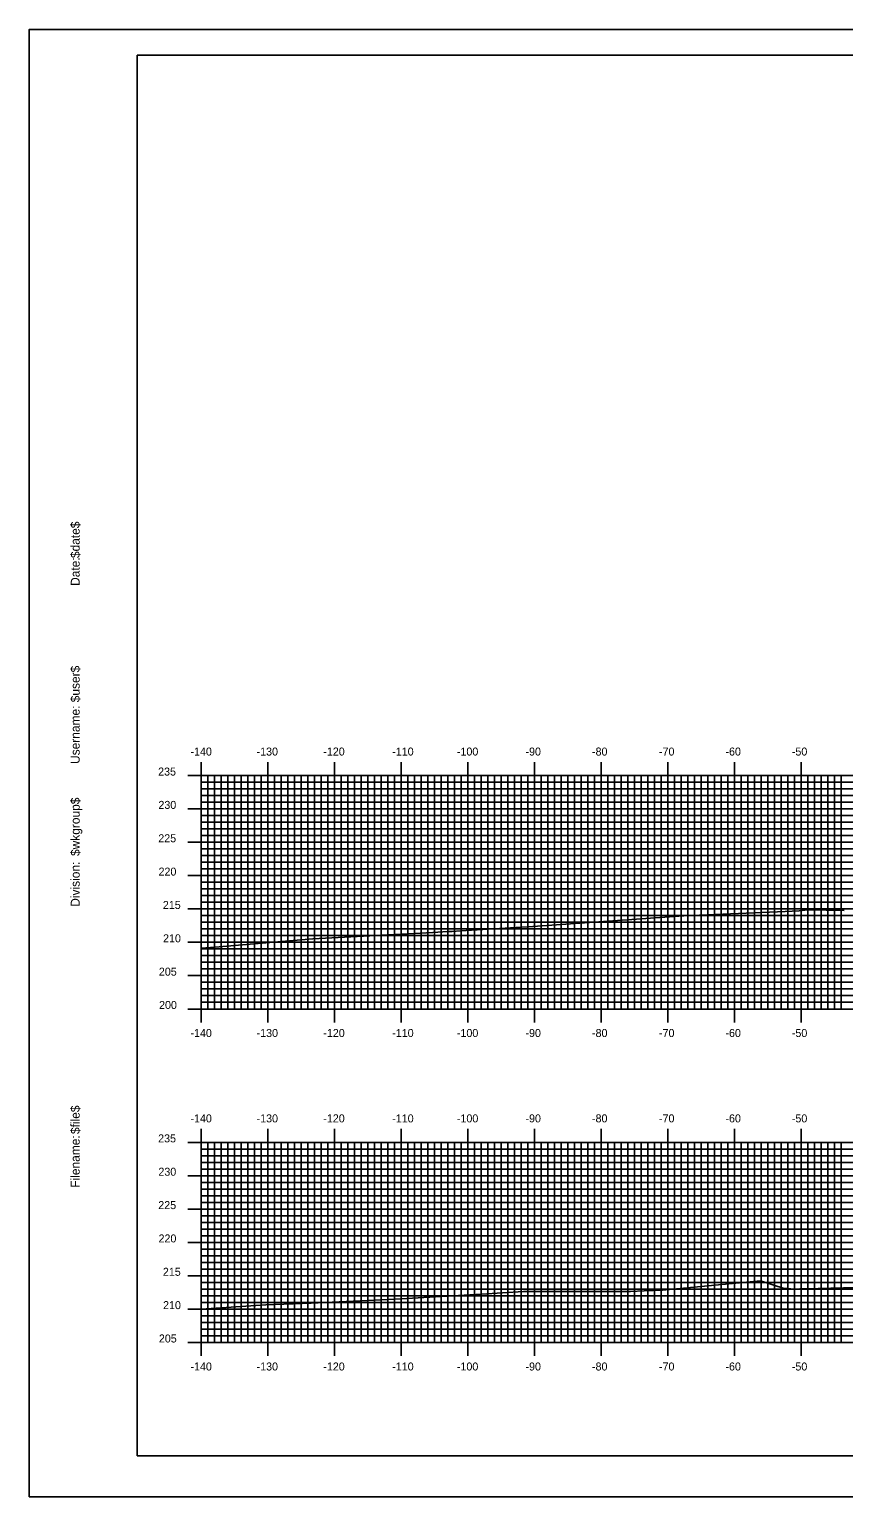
# Model space of a CAD drawing. Extents: x 851348 to 851692, y 364785 to 365005.
# Drawn here: x 851348.4 to 851470.6, y 364785.1 to 365005.1 of the extents above; entities that cross this region are included whole.
import ezdxf

# ---------------------------------------------------------------- set-up
doc = ezdxf.new("R2010")
doc.units = 0
for name, color, linetype in [('BORDER', 7, 'Continuous'), ('H_V ANNOTATION', 7, 'Continuous'), ('MAJOR', 7, 'Continuous'), ('MINOR', 7, 'Continuous'), ('PLOT BOUNDARY', 7, 'Continuous'), ('S_Roadway_Centerline', 7, 'Continuous')]:
    doc.layers.add(name, color=color, linetype=linetype)

msp = doc.modelspace()

# ---------------------------------------------------------------- linework, layer by layer
at = {"layer": 'BORDER'}
msp.add_lwpolyline([(851364.59, 364791.23), (851684.59, 364791.23), (851684.59, 365001.23), (851364.59, 365001.23)], close=True, dxfattribs=at)
at = {"layer": 'MAJOR'}
for p, q in [((851374.19, 364895.24), (851374.19, 364893.23)), ((851384.19, 364895.24), (851384.19, 364893.23)), ((851394.19, 364895.24), (851394.19, 364893.23)), ((851404.19, 364895.24), (851404.19, 364893.23)), ((851414.19, 364895.24), (851414.19, 364893.23)), ((851424.19, 364895.24), (851424.19, 364893.23)), ((851434.19, 364895.24), (851434.19, 364893.23)), ((851444.19, 364895.24), (851444.19, 364893.23)), ((851454.19, 364895.24), (851454.19, 364893.23)), ((851464.19, 364895.24), (851464.19, 364893.23)), ((851372.19, 364893.23), (851374.19, 364893.23)), ((851374.19, 364893.23), (851654.19, 364893.23)), ((851374.19, 364858.23), (851374.19, 364893.23)), ((851374.19, 364858.23), (851374.19, 364893.23)), ((851374.19, 364893.23), (851654.19, 364893.23)), ((851384.19, 364858.23), (851384.19, 364893.23)), ((851394.19, 364858.23), (851394.19, 364893.23)), ((851404.19, 364858.23), (851404.19, 364893.23)), ((851414.19, 364858.23), (851414.19, 364893.23)), ((851424.19, 364858.23), (851424.19, 364893.23)), ((851434.19, 364858.23), (851434.19, 364893.23)), ((851444.19, 364858.23), (851444.19, 364893.23)), ((851454.19, 364858.23), (851454.19, 364893.23)), ((851464.19, 364858.23), (851464.19, 364893.23)), ((851372.19, 364888.23), (851374.19, 364888.23)), ((851374.19, 364888.23), (851654.19, 364888.23)), ((851372.19, 364883.23), (851374.19, 364883.23)), ((851374.19, 364883.23), (851654.19, 364883.23)), ((851372.19, 364878.23), (851374.19, 364878.23)), ((851374.19, 364878.23), (851654.19, 364878.23)), ((851372.19, 364873.23), (851374.19, 364873.23)), ((851374.19, 364873.23), (851654.19, 364873.23)), ((851372.19, 364868.23), (851374.19, 364868.23)), ((851374.19, 364868.23), (851654.19, 364868.23)), ((851372.19, 364863.23), (851374.19, 364863.23)), ((851374.19, 364863.23), (851654.19, 364863.23)), ((851372.19, 364858.23), (851374.19, 364858.23)), ((851374.19, 364858.23), (851654.19, 364858.23)), ((851374.19, 364858.23), (851654.19, 364858.23)), ((851374.19, 364856.23), (851374.19, 364858.23)), ((851384.19, 364856.23), (851384.19, 364858.23)), ((851394.19, 364856.23), (851394.19, 364858.23)), ((851404.19, 364856.23), (851404.19, 364858.23)), ((851414.19, 364856.23), (851414.19, 364858.23)), ((851424.19, 364856.23), (851424.19, 364858.23)), ((851434.19, 364856.23), (851434.19, 364858.23)), ((851444.19, 364856.23), (851444.19, 364858.23)), ((851454.19, 364856.23), (851454.19, 364858.23)), ((851464.19, 364856.23), (851464.19, 364858.23)), ((851374.19, 364840.24), (851374.19, 364838.23)), ((851384.19, 364840.24), (851384.19, 364838.23)), ((851394.19, 364840.24), (851394.19, 364838.23)), ((851404.19, 364840.24), (851404.19, 364838.23)), ((851414.19, 364840.24), (851414.19, 364838.23)), ((851424.19, 364840.24), (851424.19, 364838.23)), ((851434.19, 364840.24), (851434.19, 364838.23)), ((851444.19, 364840.24), (851444.19, 364838.23)), ((851454.19, 364840.24), (851454.19, 364838.23)), ((851464.19, 364840.24), (851464.19, 364838.23)), ((851372.19, 364838.23), (851374.19, 364838.23)), ((851374.19, 364838.23), (851654.19, 364838.23)), ((851374.19, 364808.23), (851374.19, 364838.23)), ((851374.19, 364808.23), (851374.19, 364838.23)), ((851374.19, 364838.23), (851654.19, 364838.23)), ((851384.19, 364808.23), (851384.19, 364838.23)), ((851394.19, 364808.23), (851394.19, 364838.23)), ((851404.19, 364808.23), (851404.19, 364838.23)), ((851414.19, 364808.23), (851414.19, 364838.23)), ((851424.19, 364808.23), (851424.19, 364838.23)), ((851434.19, 364808.23), (851434.19, 364838.23)), ((851444.19, 364808.23), (851444.19, 364838.23)), ((851454.19, 364808.23), (851454.19, 364838.23)), ((851464.19, 364808.23), (851464.19, 364838.23)), ((851372.19, 364833.23), (851374.19, 364833.23)), ((851374.19, 364833.23), (851654.19, 364833.23)), ((851372.19, 364828.23), (851374.19, 364828.23)), ((851374.19, 364828.23), (851654.19, 364828.23)), ((851372.19, 364823.23), (851374.19, 364823.23)), ((851374.19, 364823.23), (851654.19, 364823.23)), ((851372.19, 364818.23), (851374.19, 364818.23)), ((851374.19, 364818.23), (851654.19, 364818.23)), ((851372.19, 364813.23), (851374.19, 364813.23)), ((851374.19, 364813.23), (851654.19, 364813.23)), ((851372.19, 364808.23), (851374.19, 364808.23)), ((851374.19, 364808.23), (851654.19, 364808.23)), ((851374.19, 364808.23), (851654.19, 364808.23)), ((851374.19, 364806.23), (851374.19, 364808.23)), ((851384.19, 364806.23), (851384.19, 364808.23)), ((851394.19, 364806.23), (851394.19, 364808.23)), ((851404.19, 364806.23), (851404.19, 364808.23)), ((851414.19, 364806.23), (851414.19, 364808.23)), ((851424.19, 364806.23), (851424.19, 364808.23)), ((851434.19, 364806.23), (851434.19, 364808.23)), ((851444.19, 364806.23), (851444.19, 364808.23)), ((851454.19, 364806.23), (851454.19, 364808.23)), ((851464.19, 364806.23), (851464.19, 364808.23))]:
    msp.add_line(p, q, dxfattribs=at)
at = {"layer": 'MINOR'}
for p, q in [((851374.19, 364892.23), (851654.19, 364892.23)), ((851374.19, 364892.23), (851376.2, 364892.23)), ((851375.19, 364858.23), (851375.19, 364893.23)), ((851376.19, 364858.23), (851376.19, 364893.23)), ((851377.19, 364858.23), (851377.19, 364893.23)), ((851378.19, 364858.23), (851378.19, 364893.23)), ((851379.19, 364858.23), (851379.19, 364893.23)), ((851380.19, 364858.23), (851380.19, 364893.23)), ((851381.19, 364858.23), (851381.19, 364893.23)), ((851382.19, 364858.23), (851382.19, 364893.23)), ((851383.19, 364858.23), (851383.19, 364893.23)), ((851385.19, 364858.23), (851385.19, 364893.23)), ((851386.19, 364858.23), (851386.19, 364893.23)), ((851387.19, 364858.23), (851387.19, 364893.23)), ((851388.19, 364858.23), (851388.19, 364893.23)), ((851389.19, 364858.23), (851389.19, 364893.23)), ((851390.19, 364858.23), (851390.19, 364893.23)), ((851391.19, 364858.23), (851391.19, 364893.23)), ((851392.19, 364858.23), (851392.19, 364893.23)), ((851393.19, 364858.23), (851393.19, 364893.23)), ((851395.19, 364858.23), (851395.19, 364893.23)), ((851396.19, 364858.23), (851396.19, 364893.23)), ((851397.19, 364858.23), (851397.19, 364893.23)), ((851398.19, 364858.23), (851398.19, 364893.23)), ((851399.19, 364858.23), (851399.19, 364893.23)), ((851400.19, 364858.23), (851400.19, 364893.23)), ((851401.19, 364858.23), (851401.19, 364893.23)), ((851402.19, 364858.23), (851402.19, 364893.23)), ((851403.19, 364858.23), (851403.19, 364893.23)), ((851405.19, 364858.23), (851405.19, 364893.23)), ((851406.19, 364858.23), (851406.19, 364893.23)), ((851407.19, 364858.23), (851407.19, 364893.23)), ((851408.19, 364858.23), (851408.19, 364893.23)), ((851409.19, 364858.23), (851409.19, 364893.23)), ((851410.19, 364858.23), (851410.19, 364893.23)), ((851411.19, 364858.23), (851411.19, 364893.23)), ((851412.19, 364858.23), (851412.19, 364893.23)), ((851413.19, 364858.23), (851413.19, 364893.23)), ((851415.19, 364858.23), (851415.19, 364893.23)), ((851416.19, 364858.23), (851416.19, 364893.23)), ((851417.19, 364858.23), (851417.19, 364893.23)), ((851418.19, 364858.23), (851418.19, 364893.23)), ((851419.19, 364858.23), (851419.19, 364893.23)), ((851420.19, 364858.23), (851420.19, 364893.23)), ((851421.19, 364858.23), (851421.19, 364893.23)), ((851422.19, 364858.23), (851422.19, 364893.23)), ((851423.19, 364858.23), (851423.19, 364893.23)), ((851425.19, 364858.23), (851425.19, 364893.23)), ((851426.19, 364858.23), (851426.19, 364893.23)), ((851427.19, 364858.23), (851427.19, 364893.23)), ((851428.19, 364858.23), (851428.19, 364893.23)), ((851429.19, 364858.23), (851429.19, 364893.23)), ((851430.19, 364858.23), (851430.19, 364893.23)), ((851431.19, 364858.23), (851431.19, 364893.23)), ((851432.19, 364858.23), (851432.19, 364893.23)), ((851433.19, 364858.23), (851433.19, 364893.23)), ((851435.19, 364858.23), (851435.19, 364893.23)), ((851436.19, 364858.23), (851436.19, 364893.23)), ((851437.19, 364858.23), (851437.19, 364893.23)), ((851438.19, 364858.23), (851438.19, 364893.23)), ((851439.19, 364858.23), (851439.19, 364893.23)), ((851440.19, 364858.23), (851440.19, 364893.23)), ((851441.19, 364858.23), (851441.19, 364893.23)), ((851442.19, 364858.23), (851442.19, 364893.23)), ((851443.19, 364858.23), (851443.19, 364893.23)), ((851445.19, 364858.23), (851445.19, 364893.23)), ((851446.19, 364858.23), (851446.19, 364893.23)), ((851447.19, 364858.23), (851447.19, 364893.23)), ((851448.19, 364858.23), (851448.19, 364893.23)), ((851449.19, 364858.23), (851449.19, 364893.23)), ((851450.19, 364858.23), (851450.19, 364893.23)), ((851451.19, 364858.23), (851451.19, 364893.23)), ((851452.19, 364858.23), (851452.19, 364893.23)), ((851453.19, 364858.23), (851453.19, 364893.23)), ((851455.19, 364858.23), (851455.19, 364893.23)), ((851456.19, 364858.23), (851456.19, 364893.23)), ((851457.19, 364858.23), (851457.19, 364893.23)), ((851458.19, 364858.23), (851458.19, 364893.23)), ((851459.19, 364858.23), (851459.19, 364893.23)), ((851460.19, 364858.23), (851460.19, 364893.23)), ((851461.19, 364858.23), (851461.19, 364893.23)), ((851462.19, 364858.23), (851462.19, 364893.23)), ((851463.19, 364858.23), (851463.19, 364893.23)), ((851465.19, 364858.23), (851465.19, 364893.23)), ((851466.19, 364858.23), (851466.19, 364893.23)), ((851467.19, 364858.23), (851467.19, 364893.23)), ((851468.19, 364858.23), (851468.19, 364893.23)), ((851469.19, 364858.23), (851469.19, 364893.23)), ((851470.19, 364858.23), (851470.19, 364893.23)), ((851374.19, 364891.23), (851654.19, 364891.23)), ((851374.19, 364891.23), (851376.2, 364891.23)), ((851374.19, 364890.23), (851654.19, 364890.23)), ((851374.19, 364890.23), (851376.2, 364890.23)), ((851374.19, 364889.23), (851654.19, 364889.23)), ((851374.19, 364889.23), (851376.2, 364889.23)), ((851374.19, 364887.23), (851654.19, 364887.23)), ((851374.19, 364887.23), (851376.2, 364887.23)), ((851374.19, 364886.23), (851654.19, 364886.23)), ((851374.19, 364886.23), (851376.2, 364886.23)), ((851374.19, 364885.23), (851654.19, 364885.23)), ((851374.19, 364885.23), (851376.2, 364885.23)), ((851374.19, 364884.23), (851654.19, 364884.23)), ((851374.19, 364884.23), (851376.2, 364884.23)), ((851374.19, 364882.23), (851654.19, 364882.23)), ((851374.19, 364882.23), (851376.2, 364882.23)), ((851374.19, 364881.23), (851654.19, 364881.23)), ((851374.19, 364881.23), (851376.2, 364881.23)), ((851374.19, 364880.23), (851654.19, 364880.23)), ((851374.19, 364880.23), (851376.2, 364880.23)), ((851374.19, 364879.23), (851654.19, 364879.23)), ((851374.19, 364879.23), (851376.2, 364879.23)), ((851374.19, 364877.23), (851654.19, 364877.23)), ((851374.19, 364877.23), (851376.2, 364877.23)), ((851374.19, 364876.23), (851654.19, 364876.23)), ((851374.19, 364876.23), (851376.2, 364876.23)), ((851374.19, 364875.23), (851654.19, 364875.23)), ((851374.19, 364875.23), (851376.2, 364875.23)), ((851374.19, 364874.23), (851654.19, 364874.23)), ((851374.19, 364874.23), (851376.2, 364874.23)), ((851374.19, 364872.23), (851654.19, 364872.23)), ((851374.19, 364872.23), (851376.2, 364872.23)), ((851374.19, 364871.23), (851654.19, 364871.23)), ((851374.19, 364871.23), (851376.2, 364871.23)), ((851374.19, 364870.23), (851654.19, 364870.23)), ((851374.19, 364870.23), (851376.2, 364870.23)), ((851374.19, 364869.23), (851654.19, 364869.23)), ((851374.19, 364869.23), (851376.2, 364869.23)), ((851374.19, 364867.23), (851654.19, 364867.23)), ((851374.19, 364867.23), (851376.2, 364867.23)), ((851374.19, 364866.23), (851654.19, 364866.23)), ((851374.19, 364866.23), (851376.2, 364866.23)), ((851374.19, 364865.23), (851654.19, 364865.23)), ((851374.19, 364865.23), (851376.2, 364865.23)), ((851374.19, 364864.23), (851654.19, 364864.23)), ((851374.19, 364864.23), (851376.2, 364864.23)), ((851374.19, 364862.23), (851654.19, 364862.23)), ((851374.19, 364862.23), (851376.2, 364862.23)), ((851374.19, 364861.23), (851654.19, 364861.23)), ((851374.19, 364861.23), (851376.2, 364861.23)), ((851374.19, 364860.23), (851654.19, 364860.23)), ((851374.19, 364860.23), (851376.2, 364860.23)), ((851374.19, 364859.23), (851654.19, 364859.23)), ((851374.19, 364859.23), (851376.2, 364859.23)), ((851374.19, 364837.23), (851654.19, 364837.23)), ((851374.19, 364837.23), (851376.2, 364837.23)), ((851375.19, 364808.23), (851375.19, 364838.23)), ((851376.19, 364808.23), (851376.19, 364838.23)), ((851377.19, 364808.23), (851377.19, 364838.23)), ((851378.19, 364808.23), (851378.19, 364838.23)), ((851379.19, 364808.23), (851379.19, 364838.23)), ((851380.19, 364808.23), (851380.19, 364838.23)), ((851381.19, 364808.23), (851381.19, 364838.23)), ((851382.19, 364808.23), (851382.19, 364838.23)), ((851383.19, 364808.23), (851383.19, 364838.23)), ((851385.19, 364808.23), (851385.19, 364838.23)), ((851386.19, 364808.23), (851386.19, 364838.23)), ((851387.19, 364808.23), (851387.19, 364838.23)), ((851388.19, 364808.23), (851388.19, 364838.23)), ((851389.19, 364808.23), (851389.19, 364838.23)), ((851390.19, 364808.23), (851390.19, 364838.23)), ((851391.19, 364808.23), (851391.19, 364838.23)), ((851392.19, 364808.23), (851392.19, 364838.23)), ((851393.19, 364808.23), (851393.19, 364838.23)), ((851395.19, 364808.23), (851395.19, 364838.23)), ((851396.19, 364808.23), (851396.19, 364838.23)), ((851397.19, 364808.23), (851397.19, 364838.23)), ((851398.19, 364808.23), (851398.19, 364838.23)), ((851399.19, 364808.23), (851399.19, 364838.23)), ((851400.19, 364808.23), (851400.19, 364838.23)), ((851401.19, 364808.23), (851401.19, 364838.23)), ((851402.19, 364808.23), (851402.19, 364838.23)), ((851403.19, 364808.23), (851403.19, 364838.23)), ((851405.19, 364808.23), (851405.19, 364838.23)), ((851406.19, 364808.23), (851406.19, 364838.23)), ((851407.19, 364808.23), (851407.19, 364838.23)), ((851408.19, 364808.23), (851408.19, 364838.23)), ((851409.19, 364808.23), (851409.19, 364838.23)), ((851410.19, 364808.23), (851410.19, 364838.23)), ((851411.19, 364808.23), (851411.19, 364838.23)), ((851412.19, 364808.23), (851412.19, 364838.23)), ((851413.19, 364808.23), (851413.19, 364838.23)), ((851415.19, 364808.23), (851415.19, 364838.23)), ((851416.19, 364808.23), (851416.19, 364838.23)), ((851417.19, 364808.23), (851417.19, 364838.23)), ((851418.19, 364808.23), (851418.19, 364838.23)), ((851419.19, 364808.23), (851419.19, 364838.23)), ((851420.19, 364808.23), (851420.19, 364838.23)), ((851421.19, 364808.23), (851421.19, 364838.23)), ((851422.19, 364808.23), (851422.19, 364838.23)), ((851423.19, 364808.23), (851423.19, 364838.23)), ((851425.19, 364808.23), (851425.19, 364838.23)), ((851426.19, 364808.23), (851426.19, 364838.23)), ((851427.19, 364808.23), (851427.19, 364838.23)), ((851428.19, 364808.23), (851428.19, 364838.23)), ((851429.19, 364808.23), (851429.19, 364838.23)), ((851430.19, 364808.23), (851430.19, 364838.23)), ((851431.19, 364808.23), (851431.19, 364838.23)), ((851432.19, 364808.23), (851432.19, 364838.23)), ((851433.19, 364808.23), (851433.19, 364838.23)), ((851435.19, 364808.23), (851435.19, 364838.23)), ((851436.19, 364808.23), (851436.19, 364838.23)), ((851437.19, 364808.23), (851437.19, 364838.23)), ((851438.19, 364808.23), (851438.19, 364838.23)), ((851439.19, 364808.23), (851439.19, 364838.23)), ((851440.19, 364808.23), (851440.19, 364838.23)), ((851441.19, 364808.23), (851441.19, 364838.23)), ((851442.19, 364808.23), (851442.19, 364838.23)), ((851443.19, 364808.23), (851443.19, 364838.23)), ((851445.19, 364808.23), (851445.19, 364838.23)), ((851446.19, 364808.23), (851446.19, 364838.23)), ((851447.19, 364808.23), (851447.19, 364838.23)), ((851448.19, 364808.23), (851448.19, 364838.23)), ((851449.19, 364808.23), (851449.19, 364838.23)), ((851450.19, 364808.23), (851450.19, 364838.23)), ((851451.19, 364808.23), (851451.19, 364838.23)), ((851452.19, 364808.23), (851452.19, 364838.23)), ((851453.19, 364808.23), (851453.19, 364838.23)), ((851455.19, 364808.23), (851455.19, 364838.23)), ((851456.19, 364808.23), (851456.19, 364838.23)), ((851457.19, 364808.23), (851457.19, 364838.23)), ((851458.19, 364808.23), (851458.19, 364838.23)), ((851459.19, 364808.23), (851459.19, 364838.23)), ((851460.19, 364808.23), (851460.19, 364838.23)), ((851461.19, 364808.23), (851461.19, 364838.23)), ((851462.19, 364808.23), (851462.19, 364838.23)), ((851463.19, 364808.23), (851463.19, 364838.23)), ((851465.19, 364808.23), (851465.19, 364838.23)), ((851466.19, 364808.23), (851466.19, 364838.23)), ((851467.19, 364808.23), (851467.19, 364838.23)), ((851468.19, 364808.23), (851468.19, 364838.23)), ((851469.19, 364808.23), (851469.19, 364838.23)), ((851470.19, 364808.23), (851470.19, 364838.23)), ((851374.19, 364836.23), (851654.19, 364836.23)), ((851374.19, 364836.23), (851376.2, 364836.23)), ((851374.19, 364835.23), (851654.19, 364835.23)), ((851374.19, 364835.23), (851376.2, 364835.23)), ((851374.19, 364834.23), (851654.19, 364834.23)), ((851374.19, 364834.23), (851376.2, 364834.23)), ((851374.19, 364832.23), (851654.19, 364832.23)), ((851374.19, 364832.23), (851376.2, 364832.23)), ((851374.19, 364831.23), (851654.19, 364831.23)), ((851374.19, 364831.23), (851376.2, 364831.23)), ((851374.19, 364830.23), (851654.19, 364830.23)), ((851374.19, 364830.23), (851376.2, 364830.23)), ((851374.19, 364829.23), (851654.19, 364829.23)), ((851374.19, 364829.23), (851376.2, 364829.23)), ((851374.19, 364827.23), (851654.19, 364827.23)), ((851374.19, 364827.23), (851376.2, 364827.23)), ((851374.19, 364826.23), (851654.19, 364826.23)), ((851374.19, 364826.23), (851376.2, 364826.23)), ((851374.19, 364825.23), (851654.19, 364825.23)), ((851374.19, 364825.23), (851376.2, 364825.23)), ((851374.19, 364824.23), (851654.19, 364824.23)), ((851374.19, 364824.23), (851376.2, 364824.23)), ((851374.19, 364822.23), (851654.19, 364822.23)), ((851374.19, 364822.23), (851376.2, 364822.23)), ((851374.19, 364821.23), (851654.19, 364821.23)), ((851374.19, 364821.23), (851376.2, 364821.23)), ((851374.19, 364820.23), (851654.19, 364820.23)), ((851374.19, 364820.23), (851376.2, 364820.23)), ((851374.19, 364819.23), (851654.19, 364819.23)), ((851374.19, 364819.23), (851376.2, 364819.23)), ((851374.19, 364817.23), (851654.19, 364817.23)), ((851374.19, 364817.23), (851376.2, 364817.23)), ((851374.19, 364816.23), (851654.19, 364816.23)), ((851374.19, 364816.23), (851376.2, 364816.23)), ((851374.19, 364815.23), (851654.19, 364815.23)), ((851374.19, 364815.23), (851376.2, 364815.23)), ((851374.19, 364814.23), (851654.19, 364814.23)), ((851374.19, 364814.23), (851376.2, 364814.23)), ((851374.19, 364812.23), (851654.19, 364812.23)), ((851374.19, 364812.23), (851376.2, 364812.23)), ((851374.19, 364811.23), (851654.19, 364811.23)), ((851374.19, 364811.23), (851376.2, 364811.23)), ((851374.19, 364810.23), (851654.19, 364810.23)), ((851374.19, 364810.23), (851376.2, 364810.23)), ((851374.19, 364809.23), (851654.19, 364809.23)), ((851374.19, 364809.23), (851376.2, 364809.23))]:
    msp.add_line(p, q, dxfattribs=at)
at = {"layer": 'PLOT BOUNDARY'}
msp.add_lwpolyline([(851348.4, 364785.11), (851688.4, 364785.11), (851688.4, 365005.11), (851348.4, 365005.11)], close=True, dxfattribs=at)
at = {"layer": 'S_Roadway_Centerline'}
for points in [[(851374.19, 364867.33), (851376.29, 364867.49), (851390.95, 364868.76), (851408.92, 364869.72), (851411.18, 364869.83), (851411.82, 364869.87), (851413.07, 364869.94), (851423.92, 364870.6), (851445.86, 364872.15), (851446.61, 364872.19), (851461.81, 364872.84), (851463.88, 364872.96), (851465.18, 364873.11), (851470.64, 364873.01)], [(851374.19, 364813.24), (851383.89, 364813.88), (851390.69, 364814.11), (851403.31, 364814.7), (851416.23, 364815.48), (851422.54, 364815.86), (851438.59, 364815.87), (851440.64, 364815.95), (851443.41, 364816.06), (851458.09, 364817.46), (851461.67, 364816.31), (851462.15, 364816.3), (851463.18, 364816.23), (851464.01, 364816.27), (851466.74, 364816.31), (851472.45, 364816.47)]]:
    msp.add_lwpolyline(points, dxfattribs=at)

# ---------------------------------------------------------------- texts
at = {"layer": 'BORDER'}
for s, p in [('$date$', (851355.96, 364925.84)), ('Date:', (851355.96, 364921.67)), ('$user$', (851355.96, 364904.22)), ('Username:', (851355.96, 364894.97)), ('$wkgroup$', (851355.96, 364881.17)), ('Division:', (851355.96, 364873.56)), ('$file$', (851355.96, 364839.48)), ('Filename:', (851355.96, 364831.43))]:
    msp.add_text(s, height=1.339, rotation=90, dxfattribs=at).set_placement(p)
at = {"layer": 'H_V ANNOTATION'}
for s, p in [('-140', (851372.58, 364896.23)), ('-130', (851382.5, 364896.23)), ('-120', (851392.51, 364896.23)), ('-110', (851402.85, 364896.23)), ('-100', (851412.55, 364896.23)), ('-90', (851422.84, 364896.23)), ('-80', (851432.82, 364896.23)), ('-70', (851442.87, 364896.23)), ('-60', (851452.84, 364896.23)), ('-50', (851462.8, 364896.23)), ('235', (851367.73, 364893.23)), ('230', (851367.77, 364888.23)), ('225', (851367.75, 364883.23)), ('220', (851367.79, 364878.23)), ('215', (851368.44, 364873.23)), ('210', (851368.47, 364868.23)), ('205', (851367.84, 364863.23)), ('200', (851367.87, 364858.23)), ('-140', (851372.58, 364854.03)), ('-130', (851382.5, 364854.03)), ('-120', (851392.51, 364854.03)), ('-110', (851402.85, 364854.03)), ('-100', (851412.55, 364854.03)), ('-90', (851422.84, 364854.03)), ('-80', (851432.82, 364854.03)), ('-70', (851442.87, 364854.03)), ('-60', (851452.84, 364854.03)), ('-50', (851462.8, 364854.03)), ('-140', (851372.58, 364841.23)), ('-130', (851382.5, 364841.23)), ('-120', (851392.51, 364841.23)), ('-110', (851402.85, 364841.23)), ('-100', (851412.55, 364841.23)), ('-90', (851422.84, 364841.23)), ('-80', (851432.82, 364841.23)), ('-70', (851442.87, 364841.23)), ('-60', (851452.84, 364841.23)), ('-50', (851462.8, 364841.23)), ('235', (851367.73, 364838.23)), ('230', (851367.77, 364833.23)), ('225', (851367.75, 364828.23)), ('220', (851367.79, 364823.23)), ('215', (851368.44, 364818.23)), ('210', (851368.47, 364813.23)), ('205', (851367.84, 364808.23)), ('-140', (851372.58, 364804.03)), ('-130', (851382.5, 364804.03)), ('-120', (851392.51, 364804.03)), ('-110', (851402.85, 364804.03)), ('-100', (851412.55, 364804.03)), ('-90', (851422.84, 364804.03)), ('-80', (851432.82, 364804.03)), ('-70', (851442.87, 364804.03)), ('-60', (851452.84, 364804.03)), ('-50', (851462.8, 364804.03))]:
    msp.add_text(s, height=1.2, dxfattribs=at).set_placement(p)
at = {"layer": 'MAJOR'}
for p in [(851374.18, 364858.23), (851374.18, 364808.23)]:
    msp.add_text('-', height=0.012, dxfattribs=at).set_placement(p)

doc.saveas('drawing.dxf')
